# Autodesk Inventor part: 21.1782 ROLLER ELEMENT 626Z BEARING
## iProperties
Created: 2007-05
Part Number: 21.1782 ROLLER ELEMENT 626Z BEARING
Material: Steel
Document SubType Name: Modeling
Designer: Andy Moles
Density: 7.85 g/cm^3
Mass: 11.475 g
Surface Area: 10.1073 cm^2
Volume: 1.46178 cm^3
Author: Andy Moles
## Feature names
1. Extrusion1
2. Extrusion2
3. Mirror1
4. Fillet1
